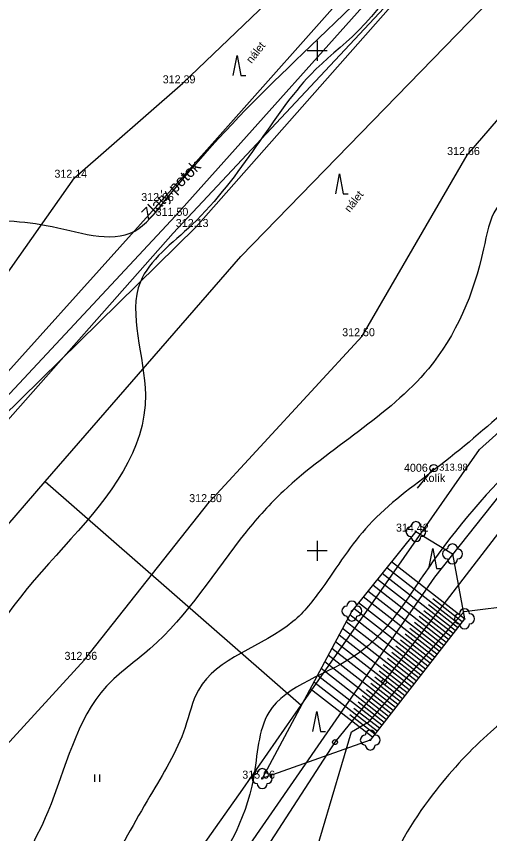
# Model space of a CAD drawing. Extents: x -504375 to -503125, y -1118000 to -1116474.
# Drawn here: x -503330.1 to -503282.7, y -1116678.3 to -1116596.5 of the extents above; entities that cross this region are included whole.
import ezdxf

# ---------------------------------------------------------------- set-up
doc = ezdxf.new("R2010")
doc.units = 0
for name, color, linetype in [('Druhy povrchů', 7, 'Continuous'), ('Podkladové mapy', 7, 'Continuous'), ('Stromy a keře', 7, 'Continuous'), ('Vodní plochy', 7, 'Continuous'), ('Vrstva 34', 7, 'Continuous'), ('Vrstva 48', 7, 'Continuous'), ('Výškopis', 7, 'Continuous'), ('Výšky bod_ pole', 7, 'Continuous'), ('Výšky bodů plotr', 7, 'Continuous'), ('Čísla bod_ pole', 7, 'Continuous')]:
    doc.layers.add(name, color=color, linetype=linetype)

msp = doc.modelspace()

# ---------------------------------------------------------------- linework, layer by layer
at = {"layer": 'Druhy povrchů'}
for p, q in [((-503322.246, -1116673.095), (-503322.246, -1116672.345)), ((-503321.746, -1116673.095), (-503321.746, -1116672.345))]:
    msp.add_line(p, q, dxfattribs=at)
for points in [[(-503397.02, -1116689.72), (-503380.03, -1116674.83), (-503363.8, -1116660.36), (-503349.88, -1116645.16), (-503336.27, -1116629.65), (-503324.3, -1116612.68), (-503313.46, -1116603.24), (-503298.24, -1116588.67), (-503283.72, -1116572.76), (-503255.76, -1116539.4)], [(-503585.68, -1116948.36), (-503569.03, -1116928.88), (-503555.79, -1116911.97), (-503526.22, -1116880.66), (-503498.19, -1116855.24), (-503492.29, -1116850.5), (-503465.52, -1116813.76), (-503435.92, -1116779.91), (-503416.58, -1116756.7), (-503397.18, -1116739.15), (-503383.4, -1116725.23), (-503367.95, -1116706.66), (-503351.89, -1116693.92), (-503339.03, -1116678.06), (-503323.29, -1116660.89), (-503310.81, -1116645.12), (-503295.5, -1116628.53), (-503285, -1116610.41), (-503272.45, -1116595.9), (-503253.91, -1116580.94), (-503230.15, -1116566.71)], [(-503308.396, -1116602.461), (-503308.021, -1116600.461), (-503307.646, -1116602.461), (-503307.146, -1116602.461)], [(-503298.154, -1116614.292), (-503297.779, -1116612.292), (-503297.404, -1116614.292), (-503296.904, -1116614.292)], [(-503288.821, -1116651.752), (-503288.446, -1116649.752), (-503288.071, -1116651.752), (-503287.571, -1116651.752)], [(-503300.426, -1116668.046), (-503300.051, -1116666.046), (-503299.676, -1116668.046), (-503299.176, -1116668.046)]]:
    msp.add_lwpolyline(points, dxfattribs=at)
at = {"layer": 'Podkladové mapy'}
for p, q in [((-503274.22, -1116575.33), (-503314.42, -1116618.21)), ((-503307.65, -1116620.55), (-503265.72, -1116577.46)), ((-503314.42, -1116618.21), (-503359.55, -1116669.22)), ((-503327.22, -1116643.07), (-503307.65, -1116620.55)), ((-503275.06, -1116635.94), (-503288.25, -1116652.61)), ((-503283.77, -1116639.85), (-503278.7, -1116635.31)), ((-503301.61, -1116665.43), (-503283.77, -1116639.85)), ((-503351.3, -1116670.8), (-503327.22, -1116643.07)), ((-503327.22, -1116643.07), (-503301.61, -1116665.43)), ((-503293.3, -1116663.09), (-503278.81, -1116644.26)), ((-503288.25, -1116652.61), (-503328.43, -1116710.6)), ((-503298.22, -1116669.12), (-503293.3, -1116663.09)), ((-503307.46, -1116673.82), (-503301.61, -1116665.43)), ((-503306.69, -1116682.17), (-503298.22, -1116669.12)), ((-503391.63, -1116793.1), (-503307.46, -1116673.82))]:
    msp.add_line(p, q, dxfattribs=at)
for centre, radius in [((-503293.3, -1116663.09), 0.25), ((-503293.3, -1116663.09), 0.005), ((-503298.22, -1116669.12), 0.25), ((-503298.22, -1116669.12), 0.005)]:
    msp.add_circle(centre, radius, dxfattribs=at)
at = {"layer": 'Stromy a keře'}
for centre in [(-503290.12, -1116648.07), (-503286.46, -1116650.3), (-503296.53, -1116656.01), (-503285.26, -1116656.78), (-503294.69, -1116668.91), (-503305.5, -1116672.77)]:
    msp.add_circle(centre, 0.05, dxfattribs=at)
for centre, start, end in [((-503290.12, -1116647.57), 0, 180), ((-503290.62, -1116648.07), 90, 270), ((-503289.62, -1116648.07), 270, 90), ((-503290.12, -1116648.57), 180, 0), ((-503286.96, -1116650.3), 90, 270), ((-503286.46, -1116649.8), 0, 180), ((-503285.96, -1116650.3), 270, 90), ((-503286.46, -1116650.8), 180, 0), ((-503297.03, -1116656.01), 90, 270), ((-503296.53, -1116655.51), 0, 180), ((-503296.03, -1116656.01), 270, 90), ((-503285.76, -1116656.78), 90, 270), ((-503285.26, -1116656.28), 0, 180), ((-503284.76, -1116656.78), 270, 90), ((-503296.53, -1116656.51), 180, 0), ((-503285.26, -1116657.28), 180, 0), ((-503295.19, -1116668.91), 90, 270), ((-503294.69, -1116668.41), 0, 180), ((-503294.19, -1116668.91), 270, 90), ((-503294.69, -1116669.41), 180, 0), ((-503305.5, -1116672.27), 0, 180), ((-503306, -1116672.77), 90, 270), ((-503305, -1116672.77), 270, 90), ((-503305.5, -1116673.27), 180, 0)]:
    msp.add_arc(centre, 0.5, start, end, dxfattribs=at)
at = {"layer": 'Vodní plochy'}
msp.add_lwpolyline([(-503334.47, -1116638.19), (-503314.17, -1116616.49), (-503290.61, -1116590.13)], dxfattribs=at)
at = {"layer": 'Vrstva 34'}
for p, q in [((-503300, -1116599), (-503300, -1116601)), ((-503299, -1116600), (-503301, -1116600)), ((-503300, -1116649), (-503300, -1116651)), ((-503299, -1116650), (-503301, -1116650))]:
    msp.add_line(p, q, dxfattribs=at)
at = {"layer": 'Vrstva 48'}
msp.add_lwpolyline([(-503300.434, -1116681.166), (-503296.556, -1116668.103), (-503294.8, -1116667.049), (-503286.048, -1116656.931), (-503285.304, -1116656.071), (-503279.91, -1116655.384), (-503275.719, -1116650.391), (-503271.777, -1116639.009), (-503265.04, -1116633.168), (-503262.143, -1116630.656), (-503250.15, -1116616.106), (-503234.98, -1116601.014), (-503231.273, -1116598.925), (-503211.098, -1116569.991), (-503210.256, -1116567.168)], dxfattribs=at)
for points in [[(-503272.713, -1116521.984), (-503284.552, -1116530.049), (-503297.613, -1116538.288), (-503309.659, -1116545.506), (-503317.719, -1116548.279), (-503326.116, -1116552.563), (-503330.483, -1116554.327), (-503334.009, -1116555.839), (-503347.343, -1116563.628), (-503356.881, -1116570.175), (-503363.037, -1116574.013), (-503376.976, -1116580.659), (-503385.521, -1116583.565), (-503391.321, -1116585.975), (-503395.157, -1116587.671), (-503409.879, -1116592.332), (-503411.663, -1116592.332), (-503418.533, -1116597.758), (-503431.06, -1116606.789)], [(-503465.065, -1116647.979), (-503454.005, -1116643.254), (-503444.995, -1116644.684), (-503441.273, -1116642.635), (-503427.473, -1116633.37), (-503425.422, -1116628.769), (-503418.525, -1116619.631), (-503414.99, -1116617.273), (-503410.82, -1116614.036), (-503399.7, -1116608.038), (-503368.713, -1116598.755), (-503365.041, -1116596.617), (-503349.145, -1116588.639), (-503333.919, -1116577.69), (-503329.925, -1116576.242), (-503314.946, -1116570.728), (-503295.077, -1116561.657), (-503258.316, -1116548.433), (-503253.777, -1116542.843), (-503252.181, -1116542.843), (-503252.181, -1116548.832), (-503257.867, -1116556.916), (-503246.784, -1116552.513), (-503240.14, -1116547.809), (-503236.915, -1116548.947)], [(-503228.261, -1116563.145), (-503229.645, -1116567.016), (-503233.265, -1116571.228), (-503245.688, -1116584.541), (-503247.935, -1116586.867), (-503252.973, -1116594.854), (-503254.135, -1116607.338), (-503261.55, -1116616.428), (-503262.857, -1116617.898), (-503273.652, -1116628.941), (-503288.12, -1116641.769), (-503294.834, -1116647.413), (-503299.542, -1116653.756), (-503302.433, -1116657.068), (-503311.897, -1116663.915), (-503313.227, -1116667.667), (-503316.736, -1116674.505), (-503325.627, -1116690.3), (-503328.511, -1116695.009), (-503335.94, -1116707.278), (-503351.034, -1116723.382), (-503365.126, -1116737.245), (-503372.674, -1116748.782), (-503373.925, -1116753.16), (-503378.551, -1116760.666), (-503382.552, -1116767.547), (-503390.579, -1116780.739), (-503398.79, -1116793.818), (-503400.908, -1116797.881), (-503402.495, -1116807.226), (-503404.198, -1116812.046), (-503412.471, -1116822.312), (-503418.387, -1116829.995), (-503420.024, -1116835.788), (-503425.814, -1116843.155), (-503430.336, -1116857.921), (-503433.683, -1116863.223), (-503434.674, -1116865.019), (-503440.926, -1116880.75), (-503445.259, -1116893.88)], [(-503481.504, -1116663.518), (-503468.547, -1116657.036), (-503463.489, -1116655.349), (-503455.413, -1116652.508), (-503447.337, -1116652.508), (-503443.352, -1116653.982), (-503430.298, -1116650.555), (-503416.187, -1116635.106), (-503410.685, -1116628.713), (-503402.504, -1116619.064), (-503381.737, -1116613.158), (-503370.807, -1116610.971), (-503361.189, -1116605.649), (-503353.61, -1116601.494), (-503341.223, -1116596.974), (-503328.544, -1116591.798), (-503324.172, -1116589.392), (-503302.385, -1116583.924), (-503293.932, -1116583.924), (-503286.266, -1116582.08), (-503284.637, -1116580.965), (-503272.933, -1116568.697), (-503269.17, -1116566.723), (-503271.089, -1116569.984), (-503281.636, -1116583.324), (-503281.636, -1116584.01), (-503265.516, -1116590.53), (-503268.945, -1116595.892), (-503268.945, -1116601.682), (-503275.976, -1116612.148), (-503282.064, -1116615.751), (-503283.352, -1116619.8), (-503288.876, -1116631.779), (-503303.377, -1116644.015), (-503307.12, -1116648.093), (-503316.743, -1116659.793), (-503321.087, -1116663.538), (-503326.965, -1116676.097), (-503331.52, -1116684.914), (-503334.134, -1116690.218), (-503342.049, -1116704.413), (-503355.564, -1116718.999), (-503373.009, -1116735.836), (-503382.317, -1116749.959), (-503386.693, -1116758.655), (-503400.779, -1116777.303), (-503409.619, -1116795.183), (-503415, -1116808.93), (-503418.611, -1116811.169), (-503424.106, -1116823.61), (-503426.69, -1116826.983), (-503429.797, -1116836.064), (-503433.946, -1116846.027), (-503439.043, -1116851.839), (-503444.852, -1116860.972), (-503445.916, -1116865.085), (-503449.799, -1116874.02), (-503458.366, -1116891.656), (-503466.054, -1116907.093), (-503467.087, -1116909.659), (-503470.52, -1116921.657)], [(-503500.793, -1116684.248), (-503495.441, -1116680.588), (-503477.217, -1116668.929), (-503469.765, -1116665.54), (-503456.961, -1116660.999), (-503454.929, -1116660.999), (-503445.173, -1116663.507), (-503440.16, -1116663.507), (-503423.051, -1116661.635), (-503408.15, -1116643.863), (-503398.378, -1116637.057), (-503392.648, -1116629.281), (-503371.711, -1116623.281), (-503344.722, -1116616.898), (-503335.508, -1116616.898), (-503327.111, -1116617.444), (-503318.26, -1116618.008), (-503315.381, -1116615.168), (-503290.617, -1116589.867), (-503290.243, -1116589.549), (-503290.538, -1116590.342), (-503300.683, -1116602.384), (-503312.519, -1116617.365), (-503317.698, -1116623.075), (-503317.198, -1116634.398), (-503334.088, -1116662.805), (-503335.757, -1116674.673), (-503338.13, -1116679.069), (-503344.017, -1116691.861), (-503347.356, -1116698.983), (-503360.449, -1116714.28), (-503364.755, -1116720.083), (-503377.404, -1116731.328), (-503383.122, -1116736.828), (-503390.673, -1116749.224), (-503402.769, -1116767.78), (-503415.526, -1116779.825), (-503422.011, -1116793.522), (-503432.295, -1116810.757), (-503433.452, -1116814.845), (-503436.422, -1116824.389), (-503442.016, -1116838.148), (-503445.44, -1116842.843), (-503455.651, -1116858.198), (-503457.49, -1116865.559), (-503458.811, -1116869.597), (-503464.787, -1116881.025), (-503469.417, -1116887.701), (-503473.366, -1116895.33), (-503475.204, -1116901.869), (-503476.43, -1116909.702), (-503479.902, -1116915.22), (-503480.991, -1116921.623), (-503488.414, -1116937.171)], [(-503228.777, -1116606.86), (-503247.87, -1116624.41), (-503250.03, -1116628.733), (-503254.714, -1116634.261), (-503259.075, -1116640.018), (-503262.555, -1116644.382), (-503263.994, -1116650.649), (-503272.717, -1116660.722), (-503282.634, -1116668.097), (-503288.112, -1116673.922), (-503293.167, -1116682.582), (-503295.386, -1116689.523), (-503299.495, -1116695.666), (-503301.478, -1116696.972), (-503309.455, -1116706.405), (-503311.196, -1116710.807), (-503320.257, -1116722.456), (-503324.189, -1116726.952), (-503334.409, -1116738.528), (-503337.358, -1116741.127), (-503347.86, -1116754.564), (-503355.556, -1116772.228), (-503356.178, -1116773.87), (-503361.611, -1116782.873), (-503368.324, -1116799.361)], [(-503226.376, -1116614.632), (-503233.107, -1116620.885), (-503240.101, -1116634.653), (-503252.255, -1116650.684), (-503264.774, -1116665.135), (-503266.507, -1116667.062), (-503278.833, -1116680.261), (-503283.648, -1116688.161), (-503287.693, -1116698.856)], [(-503265.883, -1116627.544), (-503269.693, -1116631.175), (-503278.458, -1116639.563), (-503288.462, -1116651.097), (-503292.309, -1116656.624), (-503295.894, -1116660.249), (-503304.85, -1116666.159), (-503306.392, -1116672.714), (-503319.808, -1116694.279), (-503329.527, -1116709.34), (-503332.099, -1116712.391), (-503343.962, -1116725.645), (-503346.759, -1116728.532), (-503357.339, -1116738.854), (-503363.022, -1116747.777), (-503365.151, -1116754.165), (-503367.044, -1116758.186), (-503370.891, -1116765.184), (-503373.427, -1116769.471), (-503379.022, -1116778.131), (-503381.668, -1116782.909)]]:
    msp.add_spline(points, degree=3, dxfattribs=at)
at = {"layer": 'Výškopis'}
for p, q in [((-503285.26, -1116656.78), (-503292.566, -1116651.1)), ((-503286.181, -1116657.964), (-503293.509, -1116652.268)), ((-503285.72, -1116657.372), (-503293.037, -1116651.684)), ((-503286.641, -1116658.556), (-503293.98, -1116652.851)), ((-503287.101, -1116659.148), (-503294.451, -1116653.435)), ((-503288.022, -1116660.333), (-503295.393, -1116654.602)), ((-503287.562, -1116659.741), (-503294.922, -1116654.018)), ((-503288.482, -1116660.925), (-503295.864, -1116655.186)), ((-503285.95, -1116657.668), (-503288.88, -1116655.391)), ((-503285.49, -1116657.076), (-503288.415, -1116654.802)), ((-503289.403, -1116662.109), (-503296.741, -1116656.404)), ((-503288.943, -1116661.517), (-503296.336, -1116655.769)), ((-503286.411, -1116658.26), (-503289.344, -1116655.98)), ((-503289.863, -1116662.701), (-503297.1, -1116657.076)), ((-503287.331, -1116659.445), (-503290.273, -1116657.157)), ((-503286.871, -1116658.852), (-503289.809, -1116656.569)), ((-503290.324, -1116663.293), (-503297.459, -1116657.746)), ((-503287.792, -1116660.037), (-503290.738, -1116657.746)), ((-503290.784, -1116663.885), (-503297.818, -1116658.417)), ((-503288.252, -1116660.629), (-503291.203, -1116658.335)), ((-503291.244, -1116664.478), (-503298.177, -1116659.088)), ((-503289.173, -1116661.813), (-503292.128, -1116659.515)), ((-503288.712, -1116661.221), (-503291.668, -1116658.924)), ((-503292.165, -1116665.662), (-503298.895, -1116660.429)), ((-503291.704, -1116665.07), (-503298.536, -1116659.758)), ((-503289.633, -1116662.405), (-503292.548, -1116660.139)), ((-503292.625, -1116666.254), (-503299.254, -1116661.101)), ((-503290.093, -1116662.997), (-503292.968, -1116660.763)), ((-503293.085, -1116666.846), (-503299.613, -1116661.771)), ((-503291.014, -1116664.181), (-503293.807, -1116662.01)), ((-503290.554, -1116663.589), (-503293.388, -1116661.386)), ((-503293.546, -1116667.438), (-503299.972, -1116662.442)), ((-503291.474, -1116664.774), (-503294.227, -1116662.633)), ((-503294.006, -1116668.03), (-503300.332, -1116663.113)), ((-503291.935, -1116665.366), (-503294.647, -1116663.257)), ((-503294.466, -1116668.622), (-503300.691, -1116663.784)), ((-503292.855, -1116666.55), (-503295.487, -1116664.504)), ((-503292.395, -1116665.958), (-503295.067, -1116663.881)), ((-503293.316, -1116667.142), (-503295.906, -1116665.128)), ((-503293.776, -1116667.734), (-503296.326, -1116665.752)), ((-503294.236, -1116668.326), (-503296.746, -1116666.375))]:
    msp.add_line(p, q, dxfattribs=at)
for points in [[(-503435.08, -1116738.92), (-503402.35, -1116702.54), (-503382.34, -1116679.28), (-503360.51, -1116664.43), (-503336.02, -1116637.68), (-503315.61, -1116615.01), (-503290.71, -1116587), (-503273.75, -1116568.11), (-503253.74, -1116542.47)], [(-503433.61, -1116740.76), (-503402.27, -1116708.45), (-503381.4, -1116682.04), (-503359.12, -1116667.62), (-503333.53, -1116638.6), (-503312.15, -1116617.61), (-503290.38, -1116592.97), (-503270.41, -1116570.34), (-503251.5, -1116550.22)], [(-503290.12, -1116648.07), (-503296.53, -1116656.01), (-503305.5, -1116672.77)], [(-503290.12, -1116648.07), (-503286.46, -1116650.3), (-503285.26, -1116656.78)], [(-503285.26, -1116656.78), (-503294.69, -1116668.91)], [(-503294.69, -1116668.91), (-503305.5, -1116672.77)]]:
    msp.add_lwpolyline(points, dxfattribs=at)
at = {"layer": 'Čísla bod_ pole'}
msp.add_lwpolyline([(-503289.954, -1116643.711), (-503288.34, -1116641.72)], dxfattribs=at)
for radius in [0.375, 0.0005]:
    msp.add_circle((-503288.34, -1116641.72), radius, dxfattribs=at)

# ---------------------------------------------------------------- texts
at = {"layer": 'Druhy povrchů'}
for p in [(-503306.566, -1116601.317), (-503296.743, -1116616.21)]:
    msp.add_text('nálet', height=0.7999, rotation=52.03077, dxfattribs=at).set_placement(p)
at = {"layer": 'Podkladové mapy'}
msp.add_text('Zlatý potok', height=1.15, rotation=45.00828, dxfattribs=at).set_placement((-503316.89, -1116616.97))
at = {"layer": 'Výšky bod_ pole'}
msp.add_text('313.98 ', height=0.7, dxfattribs=at).set_placement((-503287.799, -1116641.976))
at = {"layer": 'Výšky bodů plotr'}
for s, p in [('312.39 ', (-503315.46, -1116603.24)), ('312.66 ', (-503287, -1116610.41)), ('312.14 ', (-503326.3, -1116612.68)), ('312.06 ', (-503317.61, -1116615.01)), ('311.50 ', (-503316.17, -1116616.49)), ('312.13 ', (-503314.15, -1116617.61)), ('312.50 ', (-503297.5, -1116628.53)), ('312.50 ', (-503312.81, -1116645.12)), ('314.42 ', (-503292.12, -1116648.07)), ('312.56 ', (-503325.29, -1116660.89)), ('315.06 ', (-503307.5, -1116672.77))]:
    msp.add_text(s, height=0.8, dxfattribs=at).set_placement(p)
at = {"layer": 'Čísla bod_ pole'}
for s, p in [('4006', (-503291.317, -1116642.081)), ('kolík', (-503289.392, -1116643.1))]:
    msp.add_text(s, height=0.8, dxfattribs=at).set_placement(p)

doc.saveas('drawing.dxf')
